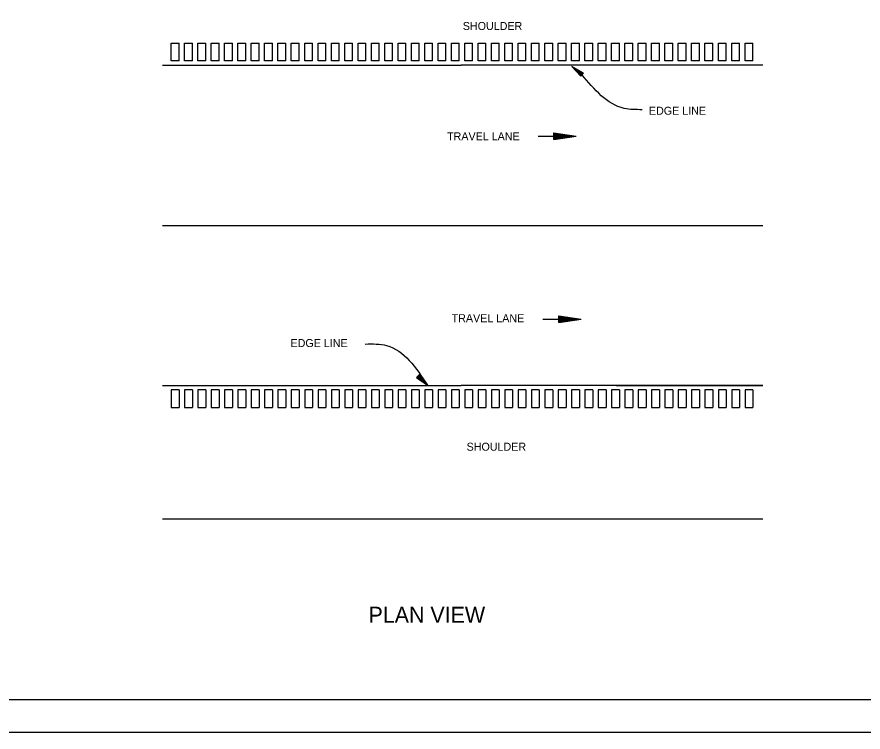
# Model space of a CAD drawing. Extents: x 1371343 to 1376243, y 378740 to 382184.
# Drawn here: x 1371902 to 1372551, y 378740 to 379289 of the extents above; entities that cross this region are included whole.
import ezdxf

# ---------------------------------------------------------------- set-up
doc = ezdxf.new("R2010")
doc.units = 0
for name, color, linetype in [('Default', 7, 'Continuous'), ('R_Draft', 7, 'Continuous'), ('SHET_Border-Lines', 7, 'Continuous')]:
    doc.layers.add(name, color=color, linetype=linetype)

msp = doc.modelspace()

# ---------------------------------------------------------------- linework, layer by layer
at = {"layer": 'Default'}
msp.add_lwpolyline([(1371342.92, 379840.49), (1371342.92, 378740.49), (1373042.92, 378740.49), (1373042.92, 379840.49)], close=True, dxfattribs=at)
at = {"layer": 'R_Draft'}
for p, q in [((1372020.39, 379255.47), (1372020.39, 379269.08)), ((1372020.39, 379269.08), (1372026.38, 379269.08)), ((1372026.38, 379255.47), (1372026.38, 379269.08)), ((1372030.62, 379255.47), (1372030.62, 379269.08)), ((1372030.62, 379269.08), (1372036.61, 379269.08)), ((1372036.61, 379255.47), (1372036.61, 379269.08)), ((1372040.86, 379255.47), (1372040.86, 379269.08)), ((1372040.86, 379269.08), (1372046.84, 379269.08)), ((1372046.84, 379255.47), (1372046.84, 379269.08)), ((1372051.09, 379255.47), (1372051.09, 379269.08)), ((1372051.09, 379269.08), (1372057.08, 379269.08)), ((1372057.08, 379255.47), (1372057.08, 379269.08)), ((1372061.32, 379255.47), (1372061.32, 379269.08)), ((1372061.32, 379269.08), (1372067.31, 379269.08)), ((1372067.31, 379255.47), (1372067.31, 379269.08)), ((1372071.56, 379255.47), (1372071.56, 379269.08)), ((1372071.56, 379269.08), (1372077.54, 379269.08)), ((1372077.54, 379255.47), (1372077.54, 379269.08)), ((1372081.79, 379255.47), (1372081.79, 379269.08)), ((1372081.79, 379269.08), (1372087.77, 379269.08)), ((1372087.77, 379255.47), (1372087.77, 379269.08)), ((1372092.02, 379255.47), (1372092.02, 379269.08)), ((1372092.02, 379269.08), (1372098.01, 379269.08)), ((1372098.01, 379255.47), (1372098.01, 379269.08)), ((1372102.25, 379255.47), (1372102.25, 379269.08)), ((1372102.25, 379269.08), (1372108.24, 379269.08)), ((1372108.24, 379255.47), (1372108.24, 379269.08)), ((1372112.49, 379255.47), (1372112.49, 379269.08)), ((1372112.49, 379269.08), (1372118.47, 379269.08)), ((1372118.47, 379255.47), (1372118.47, 379269.08)), ((1372122.72, 379255.47), (1372122.72, 379269.08)), ((1372122.72, 379269.08), (1372128.71, 379269.08)), ((1372128.71, 379255.47), (1372128.71, 379269.08)), ((1372132.95, 379255.47), (1372132.95, 379269.08)), ((1372132.95, 379269.08), (1372138.94, 379269.08)), ((1372138.94, 379255.47), (1372138.94, 379269.08)), ((1372143.18, 379255.47), (1372143.18, 379269.08)), ((1372143.18, 379269.08), (1372149.17, 379269.08)), ((1372149.17, 379255.47), (1372149.17, 379269.08)), ((1372153.42, 379255.47), (1372153.42, 379269.08)), ((1372153.42, 379269.08), (1372159.4, 379269.08)), ((1372159.4, 379255.47), (1372159.4, 379269.08)), ((1372163.65, 379255.47), (1372163.65, 379269.08)), ((1372163.65, 379269.08), (1372169.64, 379269.08)), ((1372169.64, 379255.47), (1372169.64, 379269.08)), ((1372173.88, 379255.47), (1372173.88, 379269.08)), ((1372173.88, 379255.47), (1372173.88, 379269.08)), ((1372173.88, 379269.08), (1372179.87, 379269.08)), ((1372179.87, 379255.47), (1372179.87, 379269.08)), ((1372184.12, 379255.47), (1372184.12, 379269.08)), ((1372184.12, 379269.08), (1372190.1, 379269.08)), ((1372190.1, 379255.47), (1372190.1, 379269.08)), ((1372194.35, 379255.47), (1372194.35, 379269.08)), ((1372194.35, 379269.08), (1372200.33, 379269.08)), ((1372200.33, 379255.47), (1372200.33, 379269.08)), ((1372204.58, 379255.47), (1372204.58, 379269.08)), ((1372204.58, 379269.08), (1372210.57, 379269.08)), ((1372210.57, 379255.47), (1372210.57, 379269.08)), ((1372214.81, 379255.47), (1372214.81, 379269.08)), ((1372214.81, 379269.08), (1372220.8, 379269.08)), ((1372220.8, 379255.47), (1372220.8, 379269.08)), ((1372225.05, 379255.47), (1372225.05, 379269.08)), ((1372225.05, 379269.08), (1372231.03, 379269.08)), ((1372231.03, 379255.47), (1372231.03, 379269.08)), ((1372235.28, 379255.47), (1372235.28, 379269.08)), ((1372235.28, 379269.08), (1372241.27, 379269.08)), ((1372241.27, 379255.47), (1372241.27, 379269.08)), ((1372245.51, 379255.47), (1372245.51, 379269.08)), ((1372245.51, 379269.08), (1372251.5, 379269.08)), ((1372251.5, 379255.47), (1372251.5, 379269.08)), ((1372255.75, 379255.47), (1372255.75, 379269.08)), ((1372255.75, 379269.08), (1372261.73, 379269.08)), ((1372261.73, 379255.47), (1372261.73, 379269.08)), ((1372265.98, 379255.47), (1372265.98, 379269.08)), ((1372265.98, 379269.08), (1372271.96, 379269.08)), ((1372271.96, 379255.47), (1372271.96, 379269.08)), ((1372276.21, 379255.47), (1372276.21, 379269.08)), ((1372276.21, 379269.08), (1372282.2, 379269.08)), ((1372282.2, 379255.47), (1372282.2, 379269.08)), ((1372286.44, 379255.47), (1372286.44, 379269.08)), ((1372286.44, 379269.08), (1372292.43, 379269.08)), ((1372292.43, 379255.47), (1372292.43, 379269.08)), ((1372296.68, 379255.47), (1372296.68, 379269.08)), ((1372296.68, 379269.08), (1372302.66, 379269.08)), ((1372302.66, 379255.47), (1372302.66, 379269.08)), ((1372306.91, 379255.47), (1372306.91, 379269.08)), ((1372306.91, 379269.08), (1372312.89, 379269.08)), ((1372312.89, 379255.47), (1372312.89, 379269.08)), ((1372317.14, 379255.47), (1372317.14, 379269.08)), ((1372317.14, 379269.08), (1372323.13, 379269.08)), ((1372323.13, 379255.47), (1372323.13, 379269.08)), ((1372327.37, 379255.47), (1372327.37, 379269.08)), ((1372327.37, 379269.08), (1372333.36, 379269.08)), ((1372333.36, 379255.47), (1372333.36, 379269.08)), ((1372337.61, 379255.47), (1372337.61, 379269.08)), ((1372337.61, 379269.08), (1372343.59, 379269.08)), ((1372343.59, 379255.47), (1372343.59, 379269.08)), ((1372347.84, 379255.47), (1372347.84, 379269.08)), ((1372347.84, 379269.08), (1372353.83, 379269.08)), ((1372353.83, 379255.47), (1372353.83, 379269.08)), ((1372358.07, 379255.47), (1372358.07, 379269.08)), ((1372358.07, 379269.08), (1372364.06, 379269.08)), ((1372364.06, 379255.47), (1372364.06, 379269.08)), ((1372368.31, 379255.47), (1372368.31, 379269.08)), ((1372368.31, 379269.08), (1372374.29, 379269.08)), ((1372374.29, 379255.47), (1372374.29, 379269.08)), ((1372378.54, 379255.47), (1372378.54, 379269.08)), ((1372378.54, 379269.08), (1372384.52, 379269.08)), ((1372384.52, 379255.47), (1372384.52, 379269.08)), ((1372388.77, 379255.47), (1372388.77, 379269.08)), ((1372388.77, 379269.08), (1372394.76, 379269.08)), ((1372394.76, 379255.47), (1372394.76, 379269.08)), ((1372399, 379255.47), (1372399, 379269.08)), ((1372399, 379269.08), (1372404.99, 379269.08)), ((1372404.99, 379255.47), (1372404.99, 379269.08)), ((1372409.24, 379255.47), (1372409.24, 379269.08)), ((1372409.24, 379269.08), (1372415.22, 379269.08)), ((1372415.22, 379255.47), (1372415.22, 379269.08)), ((1372419.47, 379255.47), (1372419.47, 379269.08)), ((1372419.47, 379269.08), (1372425.46, 379269.08)), ((1372425.46, 379255.47), (1372425.46, 379269.08)), ((1372429.7, 379255.47), (1372429.7, 379269.08)), ((1372429.7, 379269.08), (1372435.69, 379269.08)), ((1372435.69, 379255.47), (1372435.69, 379269.08)), ((1372439.93, 379255.47), (1372439.93, 379269.08)), ((1372439.93, 379269.08), (1372445.92, 379269.08)), ((1372445.92, 379255.47), (1372445.92, 379269.08)), ((1372450.17, 379255.47), (1372450.17, 379269.08)), ((1372450.17, 379269.08), (1372456.15, 379269.08)), ((1372456.15, 379255.47), (1372456.15, 379269.08)), ((1372460.4, 379255.47), (1372460.4, 379269.08)), ((1372460.4, 379269.08), (1372466.39, 379269.08)), ((1372466.39, 379255.47), (1372466.39, 379269.08)), ((1372013.74, 379252.06), (1372242.83, 379252.06)), ((1372026.38, 379255.47), (1372020.39, 379255.47)), ((1372036.61, 379255.47), (1372030.62, 379255.47)), ((1372046.84, 379255.47), (1372040.86, 379255.47)), ((1372057.08, 379255.47), (1372051.09, 379255.47)), ((1372067.31, 379255.47), (1372061.32, 379255.47)), ((1372077.54, 379255.47), (1372071.56, 379255.47)), ((1372087.77, 379255.47), (1372081.79, 379255.47)), ((1372098.01, 379255.47), (1372092.02, 379255.47)), ((1372108.24, 379255.47), (1372102.25, 379255.47)), ((1372118.47, 379255.47), (1372112.49, 379255.47)), ((1372128.71, 379255.47), (1372122.72, 379255.47)), ((1372138.94, 379255.47), (1372132.95, 379255.47)), ((1372149.17, 379255.47), (1372143.18, 379255.47)), ((1372159.4, 379255.47), (1372153.42, 379255.47)), ((1372169.64, 379255.47), (1372163.65, 379255.47)), ((1372179.87, 379255.47), (1372173.88, 379255.47)), ((1372190.1, 379255.47), (1372184.12, 379255.47)), ((1372200.33, 379255.47), (1372194.35, 379255.47)), ((1372210.57, 379255.47), (1372204.58, 379255.47)), ((1372220.8, 379255.47), (1372214.81, 379255.47)), ((1372231.03, 379255.47), (1372225.05, 379255.47)), ((1372241.27, 379255.47), (1372235.28, 379255.47)), ((1372474.06, 379252.06), (1372242.83, 379252.06)), ((1372251.5, 379255.47), (1372245.51, 379255.47)), ((1372261.73, 379255.47), (1372255.75, 379255.47)), ((1372271.96, 379255.47), (1372265.98, 379255.47)), ((1372282.2, 379255.47), (1372276.21, 379255.47)), ((1372292.43, 379255.47), (1372286.44, 379255.47)), ((1372302.66, 379255.47), (1372296.68, 379255.47)), ((1372312.89, 379255.47), (1372306.91, 379255.47)), ((1372323.13, 379255.47), (1372317.14, 379255.47)), ((1372333.36, 379255.47), (1372327.37, 379255.47)), ((1372334.56, 379243.67), (1372327.53, 379251.27)), ((1372336.48, 379246.08), (1372327.53, 379251.27)), ((1372343.59, 379255.47), (1372337.61, 379255.47)), ((1372353.83, 379255.47), (1372347.84, 379255.47)), ((1372364.06, 379255.47), (1372358.07, 379255.47)), ((1372374.29, 379255.47), (1372368.31, 379255.47)), ((1372384.52, 379255.47), (1372378.54, 379255.47)), ((1372394.76, 379255.47), (1372388.77, 379255.47)), ((1372404.99, 379255.47), (1372399, 379255.47)), ((1372415.22, 379255.47), (1372409.24, 379255.47)), ((1372425.46, 379255.47), (1372419.47, 379255.47)), ((1372435.69, 379255.47), (1372429.7, 379255.47)), ((1372445.92, 379255.47), (1372439.93, 379255.47)), ((1372456.15, 379255.47), (1372450.17, 379255.47)), ((1372466.39, 379255.47), (1372460.4, 379255.47)), ((1372334.72, 379243.88), (1372328.86, 379250.2)), ((1372336.33, 379245.87), (1372328.86, 379250.2)), ((1372336.15, 379245.67), (1372330.24, 379249.12)), ((1372334.9, 379244.08), (1372330.24, 379249.12)), ((1372335.05, 379244.29), (1372331.57, 379248.05)), ((1372336, 379245.46), (1372331.57, 379248.05)), ((1372335.82, 379245.26), (1372332.93, 379246.95)), ((1372335.2, 379244.49), (1372332.93, 379246.95)), ((1372335.66, 379245.05), (1372334.26, 379245.9)), ((1372335.36, 379244.7), (1372334.26, 379245.9)), ((1372334.56, 379243.67), (1372336.48, 379246.08)), ((1372313.82, 379200.26), (1372331.01, 379197.7)), ((1372313.82, 379195.12), (1372313.82, 379200.26)), ((1372313.82, 379199.85), (1372328.14, 379197.7)), ((1372313.82, 379199.39), (1372325.2, 379197.7)), ((1372301.74, 379197.7), (1372331.01, 379197.7)), ((1372313.82, 379198.98), (1372322.36, 379197.7)), ((1372313.82, 379198.55), (1372319.42, 379197.7)), ((1372313.82, 379198.11), (1372316.55, 379197.7)), ((1372313.82, 379195.12), (1372331.01, 379197.7)), ((1372313.82, 379196.88), (1372319.42, 379197.7)), ((1372313.82, 379195.96), (1372325.2, 379197.7)), ((1372313.82, 379195.55), (1372328.14, 379197.7)), ((1372313.82, 379196.42), (1372322.36, 379197.7)), ((1372313.82, 379197.27), (1372316.55, 379197.7)), ((1372013.74, 379129.27), (1372474.06, 379129.27)), ((1372305.43, 379057.41), (1372334.69, 379057.41)), ((1372317.5, 379059.94), (1372334.69, 379057.41)), ((1372317.5, 379054.83), (1372317.5, 379059.94)), ((1372317.5, 379059.53), (1372331.83, 379057.41)), ((1372317.5, 379059.1), (1372328.88, 379057.41)), ((1372317.5, 379058.66), (1372326.04, 379057.41)), ((1372317.5, 379058.23), (1372323.1, 379057.41)), ((1372317.5, 379057.82), (1372320.24, 379057.41)), ((1372317.5, 379054.83), (1372334.69, 379057.41)), ((1372317.5, 379056.57), (1372323.1, 379057.41)), ((1372317.5, 379055.67), (1372328.88, 379057.41)), ((1372317.5, 379055.24), (1372331.83, 379057.41)), ((1372317.5, 379056.11), (1372326.04, 379057.41)), ((1372317.5, 379056.98), (1372320.24, 379057.41)), ((1372210.72, 379014.79), (1372208.6, 379012.59)), ((1372208.6, 379012.59), (1372217.01, 379006.55)), ((1372208.78, 379012.77), (1372215.79, 379007.76)), ((1372208.96, 379012.95), (1372214.51, 379008.98)), ((1372209.13, 379013.13), (1372213.3, 379010.16)), ((1372209.31, 379013.31), (1372212.05, 379011.36)), ((1372209.49, 379013.51), (1372210.82, 379012.57)), ((1372209.83, 379013.85), (1372210.82, 379012.57)), ((1372210, 379014.02), (1372212.05, 379011.36)), ((1372210.18, 379014.23), (1372213.3, 379010.16)), ((1372210.36, 379014.41), (1372214.51, 379008.98)), ((1372210.54, 379014.59), (1372215.79, 379007.76)), ((1372210.72, 379014.79), (1372217.01, 379006.55)), ((1372013.74, 379006.48), (1372242.83, 379006.48)), ((1372474.06, 379006.48), (1372242.83, 379006.48)), ((1372361.65, 379006.48), (1372474.06, 379006.48)), ((1372026.38, 379003.08), (1372020.39, 379003.08)), ((1372020.39, 379003.08), (1372020.39, 378989.47)), ((1372026.38, 379003.08), (1372026.38, 378989.47)), ((1372036.61, 379003.08), (1372030.62, 379003.08)), ((1372030.62, 379003.08), (1372030.62, 378989.47)), ((1372036.61, 379003.08), (1372036.61, 378989.47)), ((1372046.84, 379003.08), (1372040.86, 379003.08)), ((1372040.86, 379003.08), (1372040.86, 378989.47)), ((1372046.84, 379003.08), (1372046.84, 378989.47)), ((1372057.08, 379003.08), (1372051.09, 379003.08)), ((1372051.09, 379003.08), (1372051.09, 378989.47)), ((1372057.08, 379003.08), (1372057.08, 378989.47)), ((1372067.31, 379003.08), (1372061.32, 379003.08)), ((1372061.32, 379003.08), (1372061.32, 378989.47)), ((1372067.31, 379003.08), (1372067.31, 378989.47)), ((1372077.54, 379003.08), (1372071.56, 379003.08)), ((1372071.56, 379003.08), (1372071.56, 378989.47)), ((1372077.54, 379003.08), (1372077.54, 378989.47)), ((1372087.77, 379003.08), (1372081.79, 379003.08)), ((1372081.79, 379003.08), (1372081.79, 378989.47)), ((1372087.77, 379003.08), (1372087.77, 378989.47)), ((1372098.01, 379003.08), (1372092.02, 379003.08)), ((1372092.02, 379003.08), (1372092.02, 378989.47)), ((1372098.01, 379003.08), (1372098.01, 378989.47)), ((1372108.24, 379003.08), (1372102.25, 379003.08)), ((1372102.25, 379003.08), (1372102.25, 378989.47)), ((1372108.24, 379003.08), (1372108.24, 378989.47)), ((1372118.47, 379003.08), (1372112.49, 379003.08)), ((1372112.49, 379003.08), (1372112.49, 378989.47)), ((1372118.47, 379003.08), (1372118.47, 378989.47)), ((1372128.71, 379003.08), (1372122.72, 379003.08)), ((1372122.72, 379003.08), (1372122.72, 378989.47)), ((1372128.71, 379003.08), (1372128.71, 378989.47)), ((1372138.94, 379003.08), (1372132.95, 379003.08)), ((1372132.95, 379003.08), (1372132.95, 378989.47)), ((1372138.94, 379003.08), (1372138.94, 378989.47)), ((1372149.17, 379003.08), (1372143.18, 379003.08)), ((1372143.18, 379003.08), (1372143.18, 378989.47)), ((1372149.17, 379003.08), (1372149.17, 378989.47)), ((1372159.4, 379003.08), (1372153.42, 379003.08)), ((1372153.42, 379003.08), (1372153.42, 378989.47)), ((1372159.4, 379003.08), (1372159.4, 378989.47)), ((1372169.64, 379003.08), (1372163.65, 379003.08)), ((1372163.65, 379003.08), (1372163.65, 378989.47)), ((1372169.64, 379003.08), (1372169.64, 378989.47)), ((1372179.87, 379003.08), (1372173.88, 379003.08)), ((1372173.88, 379003.08), (1372173.88, 378989.47)), ((1372179.87, 379003.08), (1372179.87, 378989.47)), ((1372190.1, 379003.08), (1372184.12, 379003.08)), ((1372184.12, 379003.08), (1372184.12, 378989.47)), ((1372190.1, 379003.08), (1372190.1, 378989.47)), ((1372200.33, 379003.08), (1372194.35, 379003.08)), ((1372194.35, 379003.08), (1372194.35, 378989.47)), ((1372200.33, 379003.08), (1372200.33, 378989.47)), ((1372210.57, 379003.08), (1372204.58, 379003.08)), ((1372204.58, 379003.08), (1372204.58, 378989.47)), ((1372210.57, 379003.08), (1372210.57, 378989.47)), ((1372220.8, 379003.08), (1372214.81, 379003.08)), ((1372214.81, 379003.08), (1372214.81, 378989.47)), ((1372220.8, 379003.08), (1372220.8, 378989.47)), ((1372231.03, 379003.08), (1372225.05, 379003.08)), ((1372225.05, 379003.08), (1372225.05, 378989.47)), ((1372231.03, 379003.08), (1372231.03, 378989.47)), ((1372241.27, 379003.08), (1372235.28, 379003.08)), ((1372235.28, 379003.08), (1372235.28, 378989.47)), ((1372241.27, 379003.08), (1372241.27, 378989.47)), ((1372251.5, 379003.08), (1372245.51, 379003.08)), ((1372245.51, 379003.08), (1372245.51, 378989.47)), ((1372251.5, 379003.08), (1372251.5, 378989.47)), ((1372261.73, 379003.08), (1372255.75, 379003.08)), ((1372255.75, 379003.08), (1372255.75, 378989.47)), ((1372261.73, 379003.08), (1372261.73, 378989.47)), ((1372271.96, 379003.08), (1372265.98, 379003.08)), ((1372265.98, 379003.08), (1372265.98, 378989.47)), ((1372271.96, 379003.08), (1372271.96, 378989.47)), ((1372282.2, 379003.08), (1372276.21, 379003.08)), ((1372276.21, 379003.08), (1372276.21, 378989.47)), ((1372282.2, 379003.08), (1372282.2, 378989.47)), ((1372292.43, 379003.08), (1372286.44, 379003.08)), ((1372286.44, 379003.08), (1372286.44, 378989.47)), ((1372292.43, 379003.08), (1372292.43, 378989.47)), ((1372302.66, 379003.08), (1372296.68, 379003.08)), ((1372296.68, 379003.08), (1372296.68, 378989.47)), ((1372302.66, 379003.08), (1372302.66, 378989.47)), ((1372312.89, 379003.08), (1372306.91, 379003.08)), ((1372306.91, 379003.08), (1372306.91, 378989.47)), ((1372312.89, 379003.08), (1372312.89, 378989.47)), ((1372323.13, 379003.08), (1372317.14, 379003.08)), ((1372317.14, 379003.08), (1372317.14, 378989.47)), ((1372323.13, 379003.08), (1372323.13, 378989.47)), ((1372333.36, 379003.08), (1372327.37, 379003.08)), ((1372327.37, 379003.08), (1372327.37, 378989.47)), ((1372333.36, 379003.08), (1372333.36, 378989.47)), ((1372343.59, 379003.08), (1372337.61, 379003.08)), ((1372337.61, 379003.08), (1372337.61, 378989.47)), ((1372343.59, 379003.08), (1372343.59, 378989.47)), ((1372353.83, 379003.08), (1372347.84, 379003.08)), ((1372347.84, 379003.08), (1372347.84, 378989.47)), ((1372353.83, 379003.08), (1372353.83, 378989.47)), ((1372364.06, 379003.08), (1372358.07, 379003.08)), ((1372358.07, 379003.08), (1372358.07, 378989.47)), ((1372364.06, 379003.08), (1372364.06, 378989.47)), ((1372374.29, 379003.08), (1372368.31, 379003.08)), ((1372368.31, 379003.08), (1372368.31, 378989.47)), ((1372374.29, 379003.08), (1372374.29, 378989.47)), ((1372384.52, 379003.08), (1372378.54, 379003.08)), ((1372378.54, 379003.08), (1372378.54, 378989.47)), ((1372384.52, 379003.08), (1372384.52, 378989.47)), ((1372394.76, 379003.08), (1372388.77, 379003.08)), ((1372388.77, 379003.08), (1372388.77, 378989.47)), ((1372394.76, 379003.08), (1372394.76, 378989.47)), ((1372404.99, 379003.08), (1372399, 379003.08)), ((1372399, 379003.08), (1372399, 378989.47)), ((1372404.99, 379003.08), (1372404.99, 378989.47)), ((1372415.22, 379003.08), (1372409.24, 379003.08)), ((1372409.24, 379003.08), (1372409.24, 378989.47)), ((1372415.22, 379003.08), (1372415.22, 378989.47)), ((1372425.46, 379003.08), (1372419.47, 379003.08)), ((1372419.47, 379003.08), (1372419.47, 378989.47)), ((1372425.46, 379003.08), (1372425.46, 378989.47)), ((1372435.69, 379003.08), (1372429.7, 379003.08)), ((1372429.7, 379003.08), (1372429.7, 378989.47)), ((1372435.69, 379003.08), (1372435.69, 378989.47)), ((1372445.92, 379003.08), (1372439.93, 379003.08)), ((1372439.93, 379003.08), (1372439.93, 378989.47)), ((1372445.92, 379003.08), (1372445.92, 378989.47)), ((1372456.15, 379003.08), (1372450.17, 379003.08)), ((1372450.17, 379003.08), (1372450.17, 378989.47)), ((1372456.15, 379003.08), (1372456.15, 378989.47)), ((1372466.39, 379003.08), (1372460.4, 379003.08)), ((1372460.4, 379003.08), (1372460.4, 378989.47)), ((1372466.39, 379003.08), (1372466.39, 378989.47)), ((1372020.39, 378989.47), (1372026.38, 378989.47)), ((1372030.62, 378989.47), (1372036.61, 378989.47)), ((1372040.86, 378989.47), (1372046.84, 378989.47)), ((1372051.09, 378989.47), (1372057.08, 378989.47)), ((1372061.32, 378989.47), (1372067.31, 378989.47)), ((1372071.56, 378989.47), (1372077.54, 378989.47)), ((1372081.79, 378989.47), (1372087.77, 378989.47)), ((1372092.02, 378989.47), (1372098.01, 378989.47)), ((1372102.25, 378989.47), (1372108.24, 378989.47)), ((1372112.49, 378989.47), (1372118.47, 378989.47)), ((1372122.72, 378989.47), (1372128.71, 378989.47)), ((1372132.95, 378989.47), (1372138.94, 378989.47)), ((1372143.18, 378989.47), (1372149.17, 378989.47)), ((1372153.42, 378989.47), (1372159.4, 378989.47)), ((1372163.65, 378989.47), (1372169.64, 378989.47)), ((1372173.88, 378989.47), (1372179.87, 378989.47)), ((1372184.12, 378989.47), (1372190.1, 378989.47)), ((1372194.35, 378989.47), (1372200.33, 378989.47)), ((1372204.58, 378989.47), (1372210.57, 378989.47)), ((1372214.81, 378989.47), (1372220.8, 378989.47)), ((1372225.05, 378989.47), (1372231.03, 378989.47)), ((1372235.28, 378989.47), (1372241.27, 378989.47)), ((1372245.51, 378989.47), (1372251.5, 378989.47)), ((1372255.75, 378989.47), (1372261.73, 378989.47)), ((1372265.98, 378989.47), (1372271.96, 378989.47)), ((1372276.21, 378989.47), (1372282.2, 378989.47)), ((1372286.44, 378989.47), (1372292.43, 378989.47)), ((1372296.68, 378989.47), (1372302.66, 378989.47)), ((1372306.91, 378989.47), (1372312.89, 378989.47)), ((1372317.14, 378989.47), (1372323.13, 378989.47)), ((1372327.37, 378989.47), (1372333.36, 378989.47)), ((1372337.61, 378989.47), (1372343.59, 378989.47)), ((1372347.84, 378989.47), (1372353.83, 378989.47)), ((1372358.07, 378989.47), (1372364.06, 378989.47)), ((1372368.31, 378989.47), (1372374.29, 378989.47)), ((1372378.54, 378989.47), (1372384.52, 378989.47)), ((1372388.77, 378989.47), (1372394.76, 378989.47)), ((1372399, 378989.47), (1372404.99, 378989.47)), ((1372409.24, 378989.47), (1372415.22, 378989.47)), ((1372419.47, 378989.47), (1372425.46, 378989.47)), ((1372429.7, 378989.47), (1372435.69, 378989.47)), ((1372439.93, 378989.47), (1372445.92, 378989.47)), ((1372450.17, 378989.47), (1372456.15, 378989.47)), ((1372460.4, 378989.47), (1372466.39, 378989.47)), ((1372013.74, 378904.15), (1372474.06, 378904.15))]:
    msp.add_line(p, q, dxfattribs=at)
for points in [[(1372381.61, 379218.01), (1372367.74, 379219.01), (1372335.15, 379244.98)], [(1372169.18, 379038.22), (1372185.47, 379037.1), (1372217.01, 379006.55)]]:
    msp.add_spline(points, degree=3, dxfattribs=at)
at = {"layer": 'SHET_Border-Lines'}
for points in [[(1371342.92, 378740.49), (1373042.92, 378740.49), (1373042.92, 379840.49), (1371342.92, 379840.49)], [(1371367.92, 378765.49), (1373017.92, 378765.49), (1373017.92, 379815.49), (1371367.92, 379815.49)]]:
    msp.add_lwpolyline(points, close=True, dxfattribs=at)

# ---------------------------------------------------------------- texts
at = {"layer": 'R_Draft'}
for s, height, p in [('SHOULDER', 6.14, (1372243.98, 379279.15)), ('EDGE LINE', 6.14, (1372386.7, 379214.15)), ('TRAVEL LANE', 6.1396, (1372231.92, 379194.5)), ('TRAVEL LANE', 6.1396, (1372235.43, 379054.98)), ('EDGE LINE', 6.14, (1372111.86, 379035.9)), ('SHOULDER', 6.14, (1372246.89, 378956.36)), ('PLAN VIEW ', 12.279, (1372171.67, 378824.37))]:
    msp.add_text(s, height=height, dxfattribs=at).set_placement(p)

doc.saveas('drawing.dxf')
